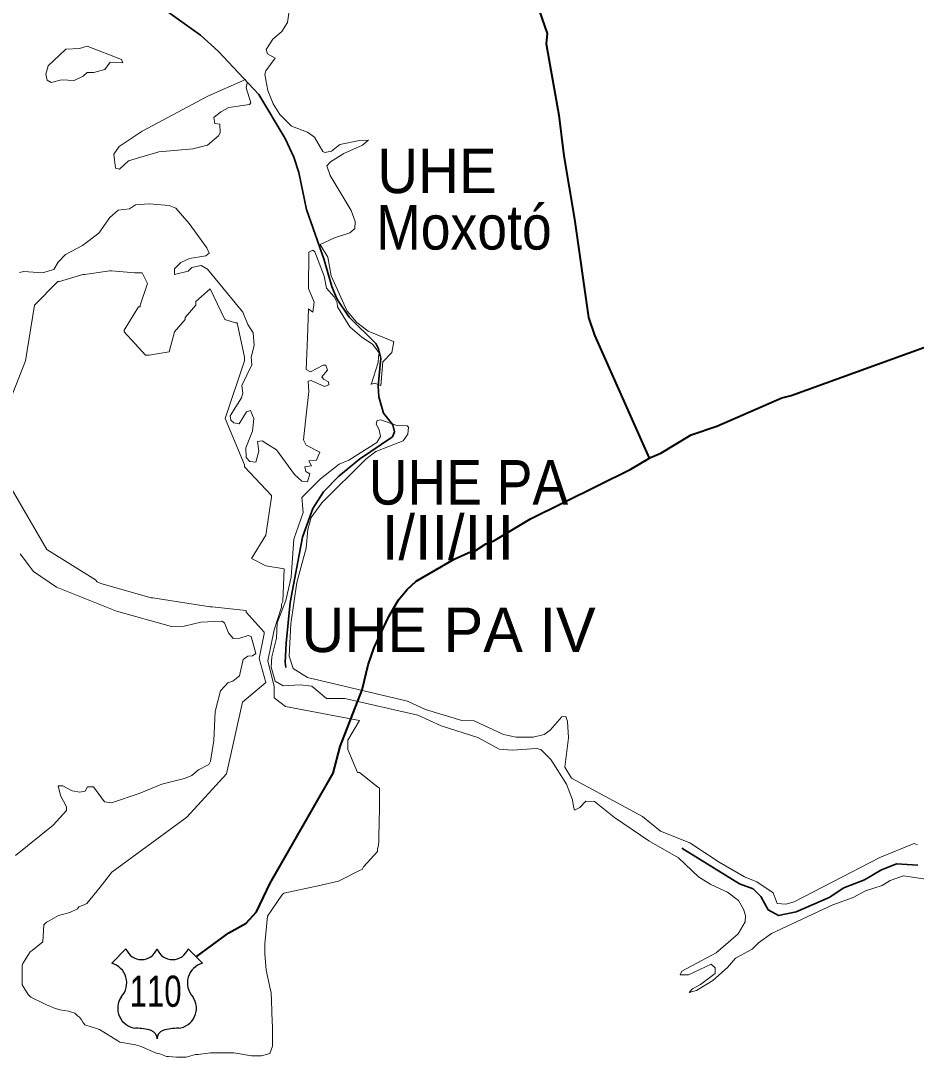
# Model space of a CAD drawing. Extents: x 553962 to 842807, y 8883888 to 9032388.
# Drawn here: x 580528 to 582541, y 8910928 to 8913256 of the extents above; entities that cross this region are included whole.
import ezdxf
from ezdxf.enums import TextEntityAlignment as Align

# ---------------------------------------------------------------- set-up
doc = ezdxf.new("R2010")
doc.units = 0
doc.header["$LTSCALE"] = 200
doc.linetypes.add('LONG_DASH_SHORT_DASH', pattern=[9.9, 6, -1.2, 1.5, -1.2])
doc.layers.add('6', color=7, linetype='Continuous', lineweight=13)

msp = doc.modelspace()

# ---------------------------------------------------------------- linework, layer by layer
at = {"layer": '6', "lineweight": 25}
for p, q in [((580732.9, 8911139.1), (580764.9, 8911171.1)), ((580904.8, 8911171.1), (580936.8, 8911139.1))]:
    msp.add_line(p, q, dxfattribs=at)
at = {"layer": '6', "lineweight": 40}
for points in [[(581692.8, 8913282), (581711.4, 8913227.6), (581709.7, 8913204.2), (581738.2, 8913043.9), (581749.4, 8912952.6), (581773.3, 8912810.4), (581804.3, 8912589.4), (581818.2, 8912550.3), (581941.2, 8912274)], [(581088.7, 8911319.2), (581230.6, 8911565.6), (581246.6, 8911626.2), (581295.9, 8911753.5), (581309.3, 8911809.4), (581322.7, 8911848.3), (581355.5, 8911918.2), (581377.7, 8911955.6), (581396.6, 8911978.5), (581417.4, 8911997.1), (581502.6, 8912046.4), (581540.6, 8912063.6), (581547.6, 8912064.2), (581573.9, 8912081.4), (581591.7, 8912087.9), (581673.8, 8912137.2), (581899.5, 8912248.7), (581943.6, 8912275.5), (581967, 8912284.7), (582035.6, 8912326.1), (582092.7, 8912345.9), (582239.2, 8912409.1), (582260, 8912414.3), (582602, 8912537.9)], [(580922.7, 8911153.1), (580996.2, 8911207.1), (581034.8, 8911228.8), (581058, 8911254.4), (581088.7, 8911319.2)]]:
    msp.add_lwpolyline(points, dxfattribs=at)
at = {"layer": '6', "linetype": 'LONG_DASH_SHORT_DASH', "lineweight": 35}
for points in [[(580854, 8913279.9), (580932.2, 8913223.8), (580972.1, 8913187.7), (581063.2, 8913090.6), (581122.5, 8912991.5), (581142, 8912949.8), (581153.2, 8912915.6), (581171, 8912832.2), (581209.9, 8912721.7), (581227.6, 8912659.4), (581239.2, 8912631.8), (581266.5, 8912590.3), (581326.2, 8912531.5), (581332.6, 8912519.4), (581337.8, 8912498.5), (581331.8, 8912436.4), (581333.1, 8912411.1), (581343.9, 8912375), (581365.1, 8912348.2), (581368.5, 8912332.5), (581364.2, 8912321.3), (581289.9, 8912271.7), (581243.5, 8912233.1), (581208.6, 8912197.7), (581185.2, 8912160.5), (581161.6, 8912095.9), (581134.3, 8911949.1), (581124.7, 8911857.9), (581122.5, 8911815.6), (581124, 8911803.1)], [(582014.6, 8911397.4), (582144.1, 8911317), (582174.9, 8911306.2), (582192.1, 8911288.9), (582208.6, 8911258.7), (582231.6, 8911246.5), (582271.2, 8911254.3), (582345.6, 8911286.3), (582378.5, 8911308.3), (582425.2, 8911326.1), (582461.6, 8911347.7), (582496.6, 8911362.4), (582544.5, 8911359.4)]]:
    msp.add_lwpolyline(points, dxfattribs=at)
at = {"layer": '6'}
for points in [[(581309.8, 8912988.2), (581309.8, 8912988.2), (581289.7, 8912987.7), (581245.5, 8912978.7), (581227.2, 8912963.4), (581212, 8912960.1), (581207.2, 8912962.6), (581188.9, 8912994.9), (581172.8, 8913005.9), (581137.1, 8913019.9), (581110.7, 8913045.9), (581096, 8913070), (581084, 8913099.8), (581076.8, 8913135.4), (581079.3, 8913144), (581100.6, 8913172.4), (581083.2, 8913182.3), (581079.8, 8913192.1), (581095.1, 8913214.9), (581115, 8913232.4), (581127.7, 8913252.7), (581131.6, 8913278.4)], [(581277.8, 8912788.2), (581279.5, 8912789.6), (581280, 8912805.1), (581271, 8912830.4), (581223.8, 8912908.6), (581216.6, 8912930.4), (581224.7, 8912939.7), (581254.8, 8912957.9), (581296.7, 8912976.6), (581308.1, 8912986.6), (581309.8, 8912988.2)], [(580525.8, 8912690.7), (580535.5, 8912693.2), (580577, 8912689.8), (580577, 8912689.8), (580602.6, 8912697.5), (580612.9, 8912714.1), (580629, 8912731.5), (580667.3, 8912751.5), (580704.2, 8912779), (580728.9, 8912814.4), (580747.1, 8912830.5), (580772.6, 8912833.5), (580786.6, 8912842.8), (580816.8, 8912845.3), (580861.8, 8912841.5), (580876.7, 8912835.6), (580907.3, 8912800.7), (580946.8, 8912745.9), (580951.8, 8912734.5), (580944.1, 8912728.4), (580907.7, 8912722.4), (580888.1, 8912713.2), (580873.7, 8912699.1), (580873.7, 8912686.1), (580905.1, 8912693.7), (580912.8, 8912702.2), (580933.6, 8912706.4), (580948.5, 8912698.3), (581027.9, 8912601.9), (581039, 8912573.9), (581050.5, 8912555), (581053.4, 8912527.1), (581046.2, 8912500.8), (581047.9, 8912483.1), (581025, 8912437.1), (581027.9, 8912419.8), (581024.9, 8912409), (580999.5, 8912368.6), (581000.8, 8912359.3), (581007.1, 8912353), (581019.3, 8912350.8), (581035.6, 8912378), (581045.2, 8912381), (581052.5, 8912362.4), (581049.6, 8912334.3), (581034.7, 8912296.8), (581034.8, 8912275.2), (581043.2, 8912266.3), (581057.1, 8912265), (581063.6, 8912289.2), (581060.7, 8912310.8), (581070.9, 8912312.5), (581081.6, 8912305.8)], [(581366.5, 8912535.8), (581309.1, 8912558.6), (581283.7, 8912578.6), (581262.3, 8912603.9), (581262.3, 8912603.9), (581225.9, 8912683.5), (581218.3, 8912725.1), (581201.7, 8912753.5), (581233.6, 8912768.4), (581267.9, 8912779.9), (581277.8, 8912788.2)], [(581172.7, 8912543.7), (581175, 8912608.9), (581185.1, 8912601.8), (581187.7, 8912624), (581174.9, 8912654.7), (581176.2, 8912736.1), (581185.3, 8912741.2), (581189.3, 8912737.1), (581210.6, 8912682.6), (581215.3, 8912655.5), (581233.2, 8912635.8), (581239.9, 8912622.3), (581240, 8912613.3), (581258.5, 8912584.3)], [(580510.6, 8912419.9), (580538.8, 8912492.6), (580559, 8912617.7), (580611.5, 8912670.2), (580615.5, 8912670.2), (580668, 8912686.4), (580672, 8912686.4), (580728.5, 8912694.4), (580732.5, 8912694.4), (580785, 8912690.4), (580793.1, 8912690.4), (580797.1, 8912690.4), (580801.1, 8912690.4), (580813.2, 8912666.2), (580797.1, 8912617.7), (580797.1, 8912613.7), (580793.1, 8912613.7), (580760.8, 8912561.2), (580760.8, 8912557.2), (580809.2, 8912504.7), (580813.2, 8912504.7), (580817.3, 8912504.7), (580861.7, 8912512.8), (580873.8, 8912557.2), (580898, 8912585.4), (580898, 8912589.5), (580922.2, 8912617.7), (580922.2, 8912621.8), (580922.2, 8912625.8), (580954.5, 8912654.1), (580986.8, 8912585.4), (581011, 8912577.4), (581015, 8912577.4), (581031.2, 8912500.7), (581031.2, 8912496.6), (581031.2, 8912492.6), (580988.2, 8912362.7), (581031.2, 8912258.5), (581031.2, 8912254.4), (581091.7, 8912189.8), (581091.7, 8912185.8), (581079.6, 8912101), (581047.3, 8912048.6)], [(581258.5, 8912584.3), (581268.3, 8912568.8), (581295.3, 8912545.3), (581319, 8912529.6), (581333.8, 8912510.2), (581332.8, 8912500.7)], [(581218.2, 8912471.5), (581214.4, 8912482.3), (581208, 8912482.9), (581179.6, 8912467.7), (581170.2, 8912473.2), (581172.7, 8912543.7)], [(581337.2, 8912437), (581338.1, 8912436.6), (581342.3, 8912490.1), (581362.3, 8912511), (581366.8, 8912535.7), (581366.5, 8912535.8)], [(581332.8, 8912500.7), (581331.5, 8912488.3), (581315.9, 8912439.5), (581316.2, 8912439.6), (581316.2, 8912440.5)], [(581169.9, 8912369.9), (581175.8, 8912423.6), (581174.5, 8912446.3), (581181.3, 8912448.5), (581211, 8912434.9), (581220.8, 8912438.5), (581220.4, 8912445.1), (581208.9, 8912451.1), (581205.5, 8912456.7), (581218.2, 8912471.5), (581218.2, 8912471.5)], [(581316.2, 8912439.6), (581324.1, 8912442.3), (581337.2, 8912437)], [(581135.5, 8911901.6), (581149.3, 8911994.6), (581170.2, 8912071.5), (581173.7, 8912113.4), (581181.2, 8912140.2), (581205.4, 8912173.1), (581304.6, 8912271.9), (581326.6, 8912288.6), (581388, 8912312.8), (581398.3, 8912327.2), (581399.7, 8912343.6), (581396.9, 8912346.6), (581374.1, 8912347), (581338.1, 8912359.7), (581329.6, 8912358.2), (581327, 8912349.8), (581333.7, 8912337.4), (581336.7, 8912322.7), (581329, 8912309.2), (581265.5, 8912268.8), (581244.2, 8912259.8), (581202.1, 8912226.9), (581160.5, 8912185.1), (581163.3, 8912151.7), (581142.6, 8912091.4), (581136.6, 8912006), (581124.1, 8911954.1), (581104.7, 8911903.6), (581102.9, 8911869.2), (581093, 8911827.2), (581091, 8911804.1), (581100.6, 8911772.3), (581118.2, 8911761.8), (581156.8, 8911764.7), (581182.7, 8911761.1), (581215.5, 8911733.5), (581257.2, 8911733.9), (581420.6, 8911696.1), (581473.7, 8911672.5), (581556.1, 8911645.9), (581603.5, 8911620.1), (581633.2, 8911618), (581687.3, 8911621.4), (581697.3, 8911618.8), (581720.2, 8911596.8), (581754.8, 8911541.3), (581768.5, 8911506.1), (581770.8, 8911491.1), (581773.4, 8911483.1), (581785.4, 8911488.5), (581798.7, 8911502.9), (581818.2, 8911502.4), (581863, 8911466.3), (581940, 8911413.8), (582006.9, 8911375.9), (582051.8, 8911333.2), (582079.1, 8911315.5), (582116.8, 8911298.3), (582141.3, 8911280.1), (582153.2, 8911260.5), (582157.4, 8911246.5), (582156.8, 8911231.9), (582140.6, 8911205), (582091.4, 8911162.7), (582014.5, 8911121.4)], [(581196.1, 8912276.3), (581200.4, 8912287), (581169.9, 8912302.8), (581163.9, 8912314.7), (581165.4, 8912328.8), (581169.9, 8912369.9)], [(581081.6, 8912305.8), (581103, 8912292.4), (581143.5, 8912237.3), (581160.1, 8912222.1), (581173.1, 8912220.7), (581178.4, 8912238.5), (581169, 8912243.4), (581167.3, 8912254.3), (581181.7, 8912256.8), (581176, 8912267.4), (581193.2, 8912269.3), (581196.1, 8912276.3)], [(580733.2, 8911343.8), (580902, 8911467.3), (580990.8, 8911564.2), (581027.1, 8911725.6), (581079.6, 8911770), (581064.5, 8911823.6), (581075.6, 8911879), (581075.6, 8911883.1), (581035.2, 8911927.5), (581035.2, 8911931.5), (580958.5, 8911939.6), (580954.5, 8911939.6), (580825.3, 8911959.8), (580821.3, 8911959.8), (580708.3, 8911992), (580700.2, 8911996.1), (580696.2, 8912000.1), (580587.3, 8912068.7), (580506.6, 8912206)], [(580896.6, 8911553.8), (580912.7, 8911561), (580928, 8911573.3), (580951, 8911585.2), (580955.3, 8911593.3), (580962.1, 8911639.2), (580965.5, 8911704.7), (580977.3, 8911751.3), (580993.9, 8911768.7), (581005.5, 8911772.6), (581020.3, 8911784.5), (581028.3, 8911821), (581038.6, 8911828.7), (581049.6, 8911829.9), (581056.8, 8911835.1), (581046.7, 8911872.7), (581039.4, 8911875.4), (581020.8, 8911869.1), (581005.8, 8911868.2), (580995.2, 8911881.4), (580986.3, 8911903.8), (580980.3, 8911907.2), (580933.2, 8911905.1), (580895.8, 8911896.2), (580867.6, 8911895.4), (580743.7, 8911929.8), (580608.6, 8911983.8), (580557.2, 8912019.4), (580527, 8912059)], [(581047.3, 8912048.6), (581079.2, 8912031.7), (581120.6, 8912025.3), (581117.4, 8911952), (581114.3, 8911945.6), (581114.3, 8911939.2), (581098.3, 8911888.2), (581083.9, 8911818.2), (581098.3, 8911761), (581098.3, 8911735.2), (581123.8, 8911716), (581289.6, 8911684.2)], [(582544.2, 8911404.8), (582536.6, 8911407.9), (582459.2, 8911376.8), (582266.9, 8911277), (582247.9, 8911272), (582228.9, 8911273), (582219.8, 8911296.8), (582183.2, 8911321.6), (582155, 8911333.2), (582098.2, 8911365.9), (582032.6, 8911409.3), (581966.1, 8911435.9), (581926.1, 8911468.6), (581766.4, 8911554.5), (581751, 8911579.8), (581759.2, 8911645), (581757, 8911682.3), (581753.9, 8911693), (581744.2, 8911692.6), (581718.2, 8911662.4), (581704.6, 8911652.6), (581679.8, 8911647.1), (581642.2, 8911646.8), (581613.1, 8911652.5), (581547.6, 8911683.5), (581519.6, 8911684), (581438.5, 8911709), (581397.4, 8911727.8), (581173.1, 8911780.9), (581140.4, 8911800.9), (581132.1, 8911829.1), (581135.5, 8911901.6)], [(581091.6, 8911074.3), (581090.1, 8911078.7), (581079.7, 8911123.2), (581076.8, 8911160.2), (581076.8, 8911182.4), (581082.7, 8911244.6), (581115.3, 8911292), (581119.7, 8911296.5), (581196.7, 8911312.8), (581242.6, 8911323.1), (581291.5, 8911348.3), (581295.9, 8911349.8), (581298.9, 8911355.7), (581330, 8911389.8), (581330, 8911395.7), (581331.5, 8911400.1), (581332.9, 8911412), (581332.9, 8911423.8), (581334.4, 8911487.5), (581334.4, 8911492), (581334.4, 8911496.4), (581334.4, 8911532), (581330, 8911534.9), (581290, 8911567.5), (581285.5, 8911567.5), (581263.3, 8911619.3), (581263.3, 8911640.1), (581289.6, 8911684.2)], [(581289.6, 8911684.2), (581263.3, 8911640.1), (581263.3, 8911619.3), (581285.5, 8911567.5), (581290, 8911567.5), (581330, 8911534.9), (581334.4, 8911532), (581334.4, 8911496.4), (581334.4, 8911492), (581334.4, 8911487.5), (581332.9, 8911423.8), (581332.9, 8911412), (581331.5, 8911400.1), (581330, 8911395.7), (581330, 8911389.8), (581298.9, 8911355.7), (581295.9, 8911349.8), (581291.5, 8911348.3), (581242.6, 8911323.1), (581196.7, 8911312.8), (581119.7, 8911296.5), (581115.3, 8911292), (581082.7, 8911244.6), (581076.8, 8911182.4), (581076.8, 8911160.2), (581079.7, 8911123.2), (581090.1, 8911078.7), (581091.6, 8911074.3)], [(580516.9, 8911381.3), (580601.1, 8911449.4), (580631.4, 8911481.8), (580631.6, 8911490.3), (580617.5, 8911516), (580612.5, 8911537.2), (580623.1, 8911537.2), (580644.2, 8911526.6), (580661.3, 8911523.2), (580673.6, 8911525.3), (580678.7, 8911535.1), (580691.8, 8911535.1), (580716.5, 8911501.6), (580732.2, 8911499.4), (580794.7, 8911520.2), (580845.5, 8911541.4), (580896.6, 8911553.8)], [(580733.2, 8911343.8), (580706.6, 8911309.8), (580677, 8911272.8), (580671.1, 8911269.8), (580659.2, 8911265.3), (580656.3, 8911260.9), (580640, 8911253.5), (580635.5, 8911252), (580625.2, 8911249.1), (580613.3, 8911246.1), (580592.6, 8911234.2), (580586.7, 8911231.3), (580580.7, 8911225.4), (580577.8, 8911186.8), (580554.1, 8911167.6), (580549.7, 8911164.6), (580533.4, 8911138), (580531.9, 8911133.5), (580531.9, 8911123.2), (580531.9, 8911095), (580531.9, 8911090.6), (580545.2, 8911068.4), (580551.1, 8911062.4), (580582.2, 8911047.6), (580588.2, 8911044.7), (580592.6, 8911043.2), (580605.9, 8911037.2), (580611.8, 8911035.8), (580616.3, 8911034.3), (580635.5, 8911031.3), (580640, 8911029.8), (580650.3, 8911026.9), (580656.3, 8911021), (580660.7, 8911018), (580665.1, 8911012.1), (580668.1, 8911006.2), (580672.6, 8911000.2), (580700.7, 8910991.3), (580705.1, 8910989.9), (580746.6, 8910964.7), (580751, 8910961.7), (580786.6, 8910955.8), (580796.9, 8910952.8), (580835.4, 8910936.5), (580841.3, 8910935.1), (580856.2, 8910929.1), (580860.6, 8910929.1), (580878.4, 8910927.7), (580884.3, 8910927.7), (580894.7, 8910927.7), (580900.6, 8910927.7), (580921.3, 8910933.6), (580927.2, 8910933.6), (580955.3, 8910938), (580967.2, 8910938), (581007.2, 8910938), (581047.2, 8910930.6), (581069.4, 8910930.6), (581088.6, 8910936.5), (581094.5, 8910952.8), (581094.5, 8910957.3), (581094.5, 8910994.3), (581093.1, 8911026.9), (581093.1, 8911032.8), (581091.6, 8911074.3)], [(581091.6, 8911074.3), (581093.1, 8911032.8), (581093.1, 8911026.9), (581094.5, 8910994.3), (581094.5, 8910957.3), (581094.5, 8910952.8), (581088.6, 8910936.5), (581069.4, 8910930.6), (581047.2, 8910930.6), (581007.2, 8910938), (580967.2, 8910938), (580955.3, 8910938), (580927.2, 8910933.6), (580921.3, 8910933.6), (580900.6, 8910927.7), (580894.7, 8910927.7), (580884.3, 8910927.7), (580878.4, 8910927.7), (580860.6, 8910929.1), (580856.2, 8910929.1), (580841.3, 8910935.1), (580835.4, 8910936.5), (580796.9, 8910952.8), (580786.6, 8910955.8), (580751, 8910961.7), (580746.6, 8910964.7), (580705.1, 8910989.9), (580700.7, 8910991.3), (580672.6, 8911000.2), (580668.1, 8911006.2), (580665.1, 8911012.1), (580660.7, 8911018), (580656.3, 8911021), (580650.3, 8911026.9), (580640, 8911029.8), (580635.5, 8911031.3), (580616.3, 8911034.3), (580611.8, 8911035.8), (580605.9, 8911037.2), (580592.6, 8911043.2), (580588.2, 8911044.7), (580582.2, 8911047.6), (580551.1, 8911062.4), (580545.2, 8911068.4), (580531.9, 8911090.6), (580531.9, 8911095), (580531.9, 8911123.2), (580531.9, 8911133.5), (580533.4, 8911138), (580549.7, 8911164.6), (580554.1, 8911167.6), (580577.8, 8911186.8), (580580.7, 8911225.4), (580586.7, 8911231.3), (580592.6, 8911234.2), (580613.3, 8911246.1), (580625.2, 8911249.1), (580635.5, 8911252), (580640, 8911253.5), (580656.3, 8911260.9), (580659.2, 8911265.3), (580671.1, 8911269.8), (580677, 8911272.8), (580706.6, 8911309.8), (580733.2, 8911343.8)], [(582014.5, 8911121.4), (582010.5, 8911113), (582029.1, 8911112.6), (582080.3, 8911136.5), (582089.3, 8911129), (582089.3, 8911116.2), (582056.3, 8911091.3), (582038, 8911081.5), (582030.9, 8911073.5), (582047.2, 8911077.7), (582084.2, 8911100), (582117.1, 8911129.1), (582134.6, 8911150.4), (582172.3, 8911170.2), (582186.7, 8911184.5), (582215.5, 8911205.5), (582353.6, 8911270.2), (582399.6, 8911286.5), (582427.2, 8911301.9), (582464.8, 8911313.9), (582482.7, 8911325), (582512.2, 8911335.3), (582681.7, 8911309.6)]]:
    msp.add_lwpolyline(points, dxfattribs=at)
for points in [[(580677.4, 8913199.3), (580754.6, 8913169.1), (580757.7, 8913161.8), (580729.4, 8913163.2), (580717.7, 8913147), (580692.7, 8913140.2), (580677.9, 8913140.2), (580669, 8913131.7), (580648.6, 8913122.4), (580619.7, 8913123.6), (580597.1, 8913117.7), (580587.8, 8913122.8), (580585.2, 8913136.5), (580590.4, 8913155), (580629.9, 8913192.5), (580660.4, 8913193.7)], [(580749.7, 8912974.1), (580801.2, 8913008.5), (580948.9, 8913087.1), (581033.9, 8913124), (581037.3, 8913116.8), (581035.2, 8913105.4), (581045.7, 8913072.2), (581042.7, 8913067.9), (580996, 8913061.1), (580977.8, 8913051.8), (580962.2, 8913039.1), (580964.6, 8913025.5), (580976, 8913023.8), (580976.9, 8913004.7), (580972.7, 8912997.5), (580948.1, 8912976.6), (580915.4, 8912968.6), (580838.8, 8912961.7), (580770.9, 8912941.3), (580750.1, 8912923.1), (580741.6, 8912925.3), (580737.8, 8912956.3)]]:
    msp.add_lwpolyline(points, close=True, dxfattribs=at)
at = {"layer": '6', "lineweight": 25}
for centre, radius, start, end in [((580799.9, 8911184.5), 37.4, 200.9593, 339.0407), ((580869.8, 8911184.5), 37.4, 200.9593, 339.0407), ((580720.5, 8911094.7), 46.1, 317.5721, 74.3689), ((580949.2, 8911094.7), 46.1, 105.6277, 222.4279), ((580791.2, 8911037.7), 44.9, 144.7373, 264.6578), ((580878.5, 8911037.7), 44.9, 275.3422, 35.2627), ((580786.8, 8910875), 118, 72.8937, 89.9006), ((580816, 8910969.7), 18.9, 357.6934, 72.9296), ((580853.7, 8910969.7), 18.9, 107.0704, 182.3065), ((580882.9, 8910875), 118, 90.0994, 107.1063)]:
    msp.add_arc(centre, radius, start, end, dxfattribs=at)

# ---------------------------------------------------------------- texts
at = {"layer": '6'}
for s, height, width, p in [('UHE', 100, 0.95, (581464.1, 8912869.1)), ('Moxotó', 100, 0.9, (581524.5, 8912742.3)), ('UHE PA', 100, 0.9, (581534.8, 8912169.4)), ('110', 70, 0.75, (580831.6, 8911041.1))]:
    msp.add_text(s, height=height, dxfattribs=dict(at, width=width)).set_placement(p, align=Align.CENTER)
for s, p in [('I/II/III', (581488.8, 8912045.7)), ('UHE PA IV', (581490, 8911837.9))]:
    msp.add_text(s, height=100, dxfattribs=at).set_placement(p, align=Align.CENTER)

doc.saveas('drawing.dxf')
